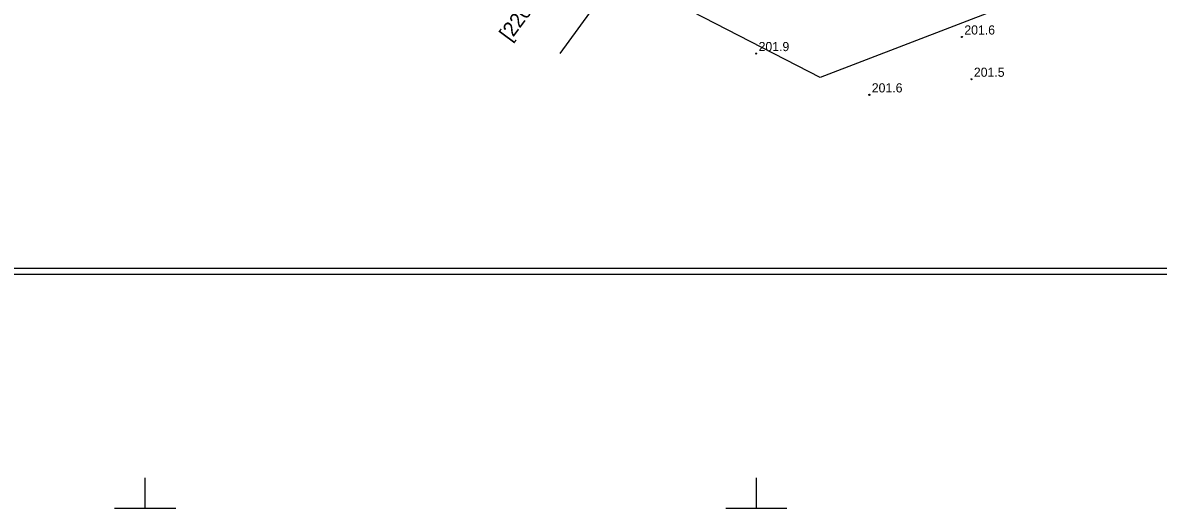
# Model space of a CAD drawing. Extents: x 6512400 to 6513200, y 6022500 to 6022750.
# Drawn here: x 6512690 to 6512782.9, y 6022500 to 6022539.7 of the extents above; entities that cross this region are included whole.
import ezdxf

# ---------------------------------------------------------------- set-up
doc = ezdxf.new("R2010")
doc.units = 0
for name, color, linetype in [('208-opis obrębu', 7, 'Continuous'), ('Miejsce błędu lub ostrzeżenia po kontroli', 7, 'Continuous'), ('Obszar opracowania', 7, 'Continuous'), ('pikieta naturalna', 7, 'Continuous'), ('pikieta naturalna-Atr2', 7, 'Continuous'), ('woda stojąca', 7, 'Continuous'), ('Wstawianie ramki sekcyjnej z opisem', 7, 'Continuous')]:
    doc.layers.add(name, color=color, linetype=linetype)

# ---------------------------------------------------------------- blocks, each defined once
blk = doc.blocks.new('PW01')
blk.add_circle((0, 0), 0.045)
blk = doc.blocks.new('RAMKA500K')
for p, q in [((300, 0), (300, 2.5)), ((350, 0), (350, 2.5)), ((297.5, 0), (302.5, 0)), ((347.5, 0), (352.5, 0))]:
    blk.add_line(p, q)

msp = doc.modelspace()

# ---------------------------------------------------------------- linework, layer by layer
at = {"layer": 'Miejsce błędu lub ostrzeżenia po kontroli'}
for points in [[(6512620.44, 6022519.14), (6512620.44, 6022719.53), (6512907.88, 6022719.53), (6512907.88, 6022519.14)], [(6512657.26, 6022519.64), (6512657.26, 6022719.03), (6512907.38, 6022719.03), (6512907.38, 6022519.64)]]:
    msp.add_lwpolyline(points, close=True, dxfattribs=at)
at = {"layer": 'Obszar opracowania'}
msp.add_lwpolyline([(6512710.98, 6022693.84), (6512748.35, 6022694.16), (6512798.11, 6022695.25), (6512807.47, 6022695.46), (6512809.66, 6022606.87), (6512863.71, 6022622.03), (6512875.13, 6022581.36), (6512755.22, 6022535.25), (6512691.61, 6022568.03), (6512709.16, 6022605.16)], close=True, dxfattribs=at)
at = {"layer": 'woda stojąca'}
msp.add_lwpolyline([(6512733.94, 6022537.22), (6512741.02, 6022546.93)], dxfattribs=at)

# ---------------------------------------------------------------- block references
at = {"layer": 'pikieta naturalna'}
for p in [(6512766.81, 6022538.58), (6512749.98, 6022537.22), (6512767.59, 6022535.12), (6512759.24, 6022533.84)]:
    msp.add_blockref('PW01', p, dxfattribs=at)
at = {"layer": 'Wstawianie ramki sekcyjnej z opisem'}
msp.add_blockref('RAMKA500K', (6512400, 6022500), dxfattribs=at)

# ---------------------------------------------------------------- texts
at = {"layer": '208-opis obrębu'}
msp.add_text('[220502_4.0005] 6', height=1.2, rotation=53.284, dxfattribs=at).set_placement((6512729.84, 6022538.17))
at = {"layer": 'pikieta naturalna-Atr2'}
for s, p in [('201.6', (6512767.01, 6022538.78)), ('201.9', (6512750.18, 6022537.42)), ('201.5', (6512767.79, 6022535.32)), ('201.6', (6512759.44, 6022534.04))]:
    msp.add_text(s, height=0.75, dxfattribs=at).set_placement(p)

doc.saveas('drawing.dxf')
